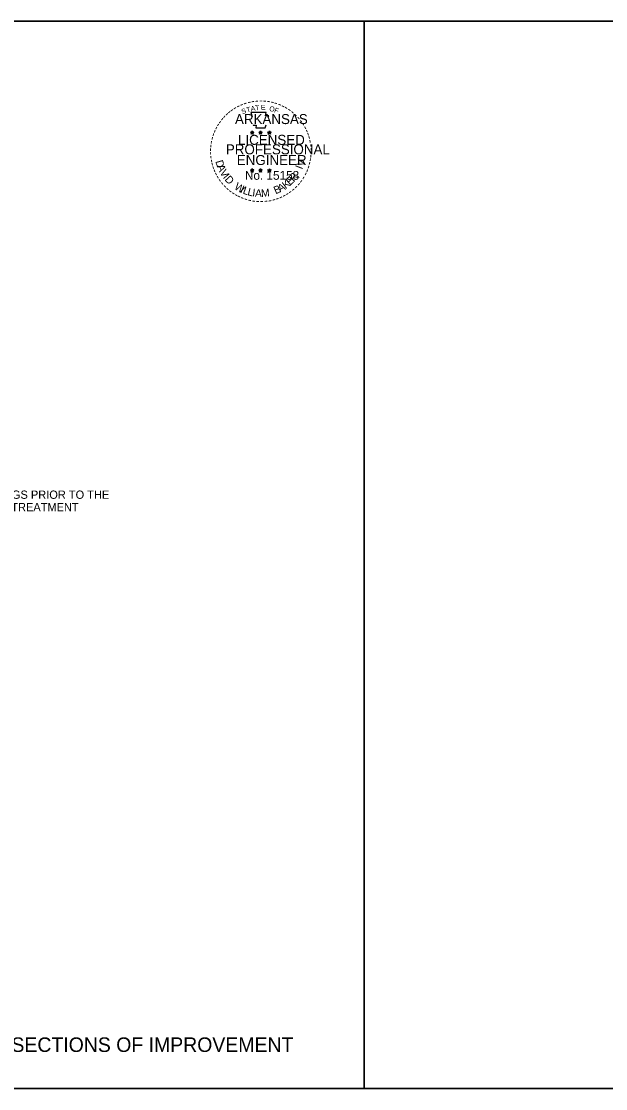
# Model space of a CAD drawing. Extents: x 96 to 721, y -177 to -41.
# Drawn here: x 480 to 540.3, y -150.6 to -40.6 of the extents above; entities that cross this region are included whole.
import ezdxf

# ---------------------------------------------------------------- set-up
doc = ezdxf.new("R2010")
doc.units = 0
for name, color, linetype in [('R_Border', 7, 'Continuous'), ('R_Border PE', 7, 'Continuous'), ('SHET_Border-Lines', 7, 'Continuous'), ('SHET_Stamp-Prelim', 7, 'Continuous')]:
    doc.layers.add(name, color=color, linetype=linetype)

msp = doc.modelspace()

# ---------------------------------------------------------------- linework, layer by layer
at = {"layer": 'R_Border'}
for points in [[(345.41, -40.58), (515.41, -40.58), (515.41, -150.58), (345.41, -150.58)], [(345.41, -40.58), (345.41, -150.58), (515.41, -150.58), (515.41, -40.58)], [(515.41, -40.58), (685.41, -40.58), (685.41, -150.58), (515.41, -150.58)], [(515.41, -40.58), (515.41, -150.58), (685.41, -150.58), (685.41, -40.58)]]:
    msp.add_lwpolyline(points, close=True, dxfattribs=at)
at = {"layer": 'R_Border PE'}
for p, q in [((503.69, -51.99), (503.87, -52.05)), ((503.69, -51.99), (503.82, -52.01)), ((503.69, -51.99), (503.82, -52.05)), ((503.76, -52.2), (503.87, -52.05)), ((503.76, -52.2), (503.83, -52.07)), ((503.76, -52.2), (503.87, -52.09)), ((503.87, -51.86), (503.85, -51.99)), ((503.87, -52.05), (503.87, -51.86)), ((503.87, -51.86), (503.9, -51.99)), ((504.05, -51.99), (503.87, -52.05)), ((503.98, -52.2), (503.87, -52.05)), ((503.98, -52.2), (503.87, -52.09)), ((504.05, -51.99), (503.91, -52.02)), ((503.98, -52.2), (503.91, -52.05)), ((504.05, -51.99), (503.95, -52.04)), ((504.55, -51.99), (504.73, -52.05)), ((504.55, -51.99), (504.69, -52.01)), ((504.55, -51.99), (504.68, -52.05)), ((504.62, -52.2), (504.73, -52.05)), ((504.62, -52.2), (504.69, -52.07)), ((504.62, -52.2), (504.73, -52.09)), ((504.73, -51.86), (504.71, -51.99)), ((504.73, -52.05), (504.73, -51.86)), ((504.73, -51.86), (504.76, -51.99)), ((504.91, -51.99), (504.73, -52.05)), ((504.84, -52.2), (504.73, -52.05)), ((504.84, -52.2), (504.73, -52.09)), ((504.91, -51.99), (504.77, -52.02)), ((504.84, -52.2), (504.77, -52.05)), ((504.91, -51.99), (504.81, -52.04)), ((505.46, -52), (505.64, -52.05)), ((505.46, -52), (505.6, -52.02)), ((505.46, -52), (505.59, -52.06)), ((505.53, -52.21), (505.64, -52.05)), ((505.53, -52.21), (505.6, -52.08)), ((505.53, -52.21), (505.64, -52.09)), ((505.64, -51.87), (505.62, -52)), ((505.64, -52.05), (505.64, -51.87)), ((505.64, -51.87), (505.67, -51.99)), ((505.82, -52), (505.64, -52.05)), ((505.75, -52.21), (505.64, -52.05)), ((505.75, -52.21), (505.64, -52.1)), ((505.82, -52), (505.68, -52.02)), ((505.75, -52.21), (505.68, -52.06)), ((505.82, -52), (505.72, -52.05)), ((503.69, -55.9), (503.87, -55.95)), ((503.69, -55.9), (503.82, -55.92)), ((503.69, -55.9), (503.81, -55.96)), ((503.76, -56.11), (503.87, -55.95)), ((503.76, -56.11), (503.83, -55.98)), ((503.76, -56.11), (503.87, -55.99)), ((503.87, -55.76), (503.85, -55.89)), ((503.87, -55.95), (503.87, -55.76)), ((503.87, -55.76), (503.9, -55.89)), ((504.05, -55.9), (503.87, -55.95)), ((503.98, -56.11), (503.87, -55.95)), ((503.98, -56.11), (503.87, -56)), ((504.05, -55.9), (503.9, -55.92)), ((503.98, -56.11), (503.91, -55.96)), ((504.05, -55.9), (503.95, -55.95)), ((504.55, -55.9), (504.73, -55.95)), ((504.55, -55.9), (504.68, -55.92)), ((504.55, -55.9), (504.67, -55.96)), ((504.62, -56.11), (504.73, -55.95)), ((504.62, -56.11), (504.69, -55.98)), ((504.62, -56.11), (504.73, -55.99)), ((504.73, -55.76), (504.71, -55.89)), ((504.73, -55.95), (504.73, -55.76)), ((504.73, -55.76), (504.76, -55.89)), ((504.91, -55.9), (504.73, -55.95)), ((504.84, -56.11), (504.73, -55.95)), ((504.84, -56.11), (504.73, -56)), ((504.91, -55.9), (504.76, -55.92)), ((504.84, -56.11), (504.77, -55.96)), ((504.91, -55.9), (504.81, -55.95)), ((505.46, -55.9), (505.64, -55.96)), ((505.46, -55.9), (505.59, -55.92)), ((505.46, -55.9), (505.59, -55.96)), ((505.53, -56.11), (505.64, -55.96)), ((505.53, -56.11), (505.6, -55.98)), ((505.53, -56.11), (505.64, -56)), ((505.64, -55.77), (505.62, -55.9)), ((505.64, -55.96), (505.64, -55.77)), ((505.64, -55.77), (505.67, -55.9)), ((505.82, -55.9), (505.64, -55.96)), ((505.75, -56.11), (505.64, -55.96)), ((505.75, -56.11), (505.64, -56)), ((505.82, -55.9), (505.67, -55.93)), ((505.75, -56.11), (505.68, -55.96)), ((505.82, -55.9), (505.72, -55.95))]:
    msp.add_line(p, q, dxfattribs=at)
for points in [[(503.72, -49.99), (503.85, -50.42)], [(505.53, -50.47), (505.6, -50.32), (505.25, -50.33), (505.32, -49.99), (503.72, -49.99)], [(503.97, -51.24), (503.97, -51.28), (504.26, -51.29), (504.23, -51.54), (505.2, -51.54), (505.3, -51.26)], [(503.87, -51.86), (503.98, -52.2), (503.69, -51.99), (504.05, -51.99), (503.76, -52.2), (503.87, -51.86)], [(504.73, -51.86), (504.84, -52.2), (504.55, -51.99), (504.91, -51.99), (504.62, -52.2), (504.73, -51.86)], [(505.64, -51.87), (505.75, -52.21), (505.46, -52), (505.82, -52), (505.53, -52.21), (505.64, -51.87)], [(503.87, -55.76), (503.98, -56.11), (503.69, -55.9), (504.05, -55.9), (503.76, -56.11), (503.87, -55.76)], [(504.73, -55.76), (504.84, -56.11), (504.55, -55.9), (504.91, -55.9), (504.62, -56.11), (504.73, -55.76)], [(505.64, -55.77), (505.75, -56.11), (505.46, -55.9), (505.82, -55.9), (505.53, -56.11), (505.64, -55.77)]]:
    msp.add_lwpolyline(points, dxfattribs=at)
for centre, radius in [((503.87, -52.05), 0.0888), ((503.87, -52.05), 0.0745), ((503.87, -52.05), 0.0597), ((503.87, -52.05), 0.0511), ((503.87, -52.05), 0.0385), ((503.87, -52.05), 0.0255), ((503.87, -52.05), 0.0153), ((504.73, -52.05), 0.0888), ((504.73, -52.05), 0.0745), ((504.73, -52.05), 0.0597), ((504.73, -52.05), 0.0511), ((504.73, -52.05), 0.0385), ((504.73, -52.05), 0.0255), ((504.73, -52.05), 0.0153), ((505.64, -52.05), 0.0888), ((505.64, -52.05), 0.0745), ((505.64, -52.05), 0.0597), ((505.64, -52.05), 0.0511), ((505.64, -52.05), 0.0385), ((505.64, -52.05), 0.0255), ((505.64, -52.05), 0.0153), ((503.87, -55.95), 0.0888), ((503.87, -55.95), 0.0745), ((503.87, -55.95), 0.0597), ((503.87, -55.95), 0.0511), ((503.87, -55.95), 0.0385), ((503.87, -55.95), 0.0255), ((503.87, -55.95), 0.0153), ((504.73, -55.95), 0.0888), ((504.73, -55.95), 0.0745), ((504.73, -55.95), 0.0597), ((504.73, -55.95), 0.0511), ((504.73, -55.95), 0.0385), ((504.73, -55.95), 0.0255), ((504.73, -55.95), 0.0153), ((505.64, -55.96), 0.0888), ((505.64, -55.96), 0.0745), ((505.64, -55.96), 0.0597), ((505.64, -55.96), 0.0511), ((505.64, -55.96), 0.0385), ((505.64, -55.96), 0.0255), ((505.64, -55.96), 0.0153)]:
    msp.add_circle(centre, radius, dxfattribs=at)

# ---------------------------------------------------------------- texts
for s, height, rotation, p in [('-', 0.825, 34.0636, (502.11, -49.9)), ('-', 0.825, 28.7918, (502.42, -49.71)), ('-', 0.825, 24.3072, (502.74, -49.55)), ('-', 0.825, 19.1761, (503.07, -49.41)), ('T', 0.516, 16.4036, (503.34, -49.99)), ('-', 0.825, 13.6302, (503.46, -49.29)), ('A', 0.516, 11.2132, (503.76, -49.86)), ('-', 0.825, 10.2193, (503.81, -49.2)), ('T', 0.516, 6.0228, (504.2, -49.77)), ('-', 0.825, 5.8968, (504.18, -49.15)), ('-', 0.825, 0.1862, (504.58, -49.11)), ('E', 0.516, 0.8323, (504.77, -49.71)), ('-', 0.825, 357.743, (504.95, -49.11)), ('-', 0.825, 352.1617, (505.34, -49.14)), ('O', 0.516, 350.4515, (505.6, -49.82)), ('-', 0.825, 347.2049, (505.71, -49.2)), ('F', 0.516, 340.0707, (506.09, -49.94)), ('-', 0.825, 342.3362, (506.03, -49.28)), ('-', 0.825, 337.8551, (506.41, -49.4)), ('-', 0.825, 334.1211, (506.74, -49.54)), ('-', 0.825, 329.6409, (507.04, -49.68)), ('-', 0.825, 50.6142, (500.9, -51.01)), ('-', 0.825, 48.4231, (501.11, -50.76)), ('-', 0.825, 42.9622, (501.34, -50.52)), ('-', 0.825, 38.9507, (501.56, -50.3)), ('-', 0.825, 36.2317, (501.81, -50.11)), ('S', 0.516, 21.594, (502.87, -50.16)), ('-', 0.825, 325.8627, (507.37, -49.87)), ('-', 0.825, 320.5297, (507.68, -50.09)), ('-', 0.825, 315.5786, (507.99, -50.34)), ('-', 0.825, 309.8797, (508.29, -50.62)), ('-', 0.825, 62.8713, (500.36, -51.89)), ('-', 0.825, 58.0706, (500.52, -51.58)), ('-', 0.825, 54.2325, (500.69, -51.31)), ('-', 0.825, 306.6522, (508.56, -50.93)), ('-', 0.722, 303.6753, (508.81, -51.23)), ('-', 0.825, 299.6684, (508.97, -51.54)), ('-', 0.825, 75.461, (500.01, -52.9)), ('-', 0.825, 72.3945, (500.11, -52.53)), ('-', 0.825, 67.7743, (500.23, -52.21)), ('-', 0.825, 294.6628, (509.14, -51.86)), ('-', 0.825, 290.5728, (509.27, -52.15)), ('-', 0.825, 285.1233, (509.39, -52.45)), ('-', 0.825, 89.0622, (499.89, -53.99)), ('-', 0.825, 85.1863, (499.91, -53.63)), ('-', 0.825, 81.2013, (499.94, -53.27)), ('-', 0.825, 280.5493, (509.49, -52.83)), ('-', 0.825, 276.5962, (509.58, -53.23)), ('-', 0.825, 274.3301, (509.61, -53.6)), ('-', 0.825, 94.1959, (499.91, -54.36)), ('-', 0.825, 98.9479, (499.95, -54.71)), ('-', 0.825, 101.7149, (500.02, -55.08)), ('D', 0.794, 286.2848, (500.06, -55.01)), ('V', 0.794, 72.6573, (509.13, -55.61)), ('-', 0.825, 260.9953, (509.58, -54.61)), ('-', 0.825, 263.5172, (509.62, -54.27)), ('-', 0.825, 269.9407, (509.63, -53.93)), ('-', 0.825, 105.4578, (500.1, -55.39)), ('-', 0.825, 109.0874, (500.21, -55.72)), ('-', 0.825, 114.0643, (500.34, -56.02)), ('A', 0.794, 292.7835, (500.21, -55.53)), ('V', 0.794, 300.7936, (500.48, -56.14)), ('I', 0.794, 69.0301, (509.02, -55.89)), ('-', 0.825, 247.8887, (509.32, -55.68)), ('-', 0.825, 252.8681, (509.43, -55.33)), ('-', 0.825, 255.7626, (509.52, -54.96)), ('-', 0.825, 115.7289, (500.5, -56.34)), ('-', 0.825, 120.4471, (500.68, -56.64)), ('-', 0.825, 125.8934, (500.89, -56.93)), ('-', 0.825, 130.7181, (501.13, -57.22)), ('I', 0.794, 308.3502, (500.8, -56.67)), ('D', 0.794, 311.9774, (500.98, -56.91)), ('W', 0.794, 328.0731, (501.95, -57.82)), ('K', 0.794, 36.9143, (507.32, -57.89)), ('E', 0.794, 44.0175, (507.79, -57.54)), ('R', 0.794, 50.3651, (508.17, -57.17)), (',', 0.794, 57.4684, (508.54, -56.72)), ('-', 0.825, 233.8452, (508.77, -56.73)), ('-', 0.825, 239.0712, (508.98, -56.39)), ('-', 0.825, 244.6197, (509.18, -56)), ('-', 0.825, 134.2238, (501.4, -57.5)), ('-', 0.825, 138.9338, (501.67, -57.74)), ('-', 0.825, 144.6463, (501.95, -57.95)), ('-', 0.825, 148.0898, (502.24, -58.14)), ('I', 0.794, 336.6877, (502.57, -58.19)), ('L', 0.794, 340.3149, (502.84, -58.31)), ('L', 0.794, 346.6625, (503.33, -58.49)), ('I', 0.794, 353.0101, (503.85, -58.61)), ('A', 0.794, 356.6373, (504.14, -58.66)), ('M', 0.794, 4.6473, (504.81, -58.69)), ('B', 0.794, 22.8589, (506.28, -58.41)), ('A', 0.794, 28.9042, (506.75, -58.22)), ('-', 0.825, 212.2491, (507.47, -58.01)), ('-', 0.825, 215.7363, (507.75, -57.81)), ('-', 0.825, 221.0851, (508.03, -57.57)), ('-', 0.825, 225.7653, (508.3, -57.31)), ('-', 0.825, 231.2538, (508.55, -57.02)), ('-', 0.825, 151.5704, (502.54, -58.31)), ('-', 0.825, 154.6002, (502.81, -58.43)), ('-', 0.825, 158.5612, (503.13, -58.56)), ('-', 0.825, 162.7983, (503.49, -58.67)), ('-', 0.825, 167.5555, (503.86, -58.76)), ('-', 0.825, 173.1155, (504.25, -58.82)), ('-', 0.825, 176.5183, (504.64, -58.84)), ('-', 0.825, 181.5918, (505.02, -58.83)), ('-', 0.825, 185.8167, (505.44, -58.79)), ('-', 0.825, 191.2858, (505.82, -58.73)), ('-', 0.825, 195.4743, (506.2, -58.62)), ('-', 0.825, 199.4643, (506.54, -58.5)), ('-', 0.825, 204.2516, (506.86, -58.36)), ('-', 0.825, 207.3568, (507.19, -58.19))]:
    msp.add_text(s, height=height, rotation=rotation, dxfattribs=at).set_placement(p)
for s, height, p in [('ARKANSAS', 1.031, (502.09, -51.17)), ('LICENSED', 1.031, (502.4, -53.31)), ('PROFESSIONAL', 1.0312, (501.15, -54.29)), ('ENGINEER', 1.031, (502.28, -55.39)), ('No. 15158', 0.906, (503.12, -56.91)), ('AAMU', 0.0000103, (504.7, -58.69))]:
    msp.add_text(s, height=height, dxfattribs=at).set_placement(p)
at = {"layer": 'SHET_Border-Lines'}
for s, p in [('REMOVE PERMAMENT PAVEMENT MARKINGS PRIOR TO THE ', (455.27, -89.79)), ('PLACEMENT OF HIGH FRICTION SURFACE TREATMENT', (455.27, -91.07))]:
    msp.add_text(s, height=0.85, dxfattribs=at).set_placement(p)
at = {"layer": 'SHET_Stamp-Prelim'}
msp.add_text('TYPICAL SECTIONS OF IMPROVEMENT', height=1.5, dxfattribs=at).set_placement((470.11, -146.8))

doc.saveas('drawing.dxf')
